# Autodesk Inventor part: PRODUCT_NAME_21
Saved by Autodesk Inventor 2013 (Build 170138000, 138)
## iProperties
Created: 2012-12
Part Number: PRODUCT_NAME_21
Material: Générique
Document SubType Name: Modeling
Designer: jost thierry
Density: 1 g/cm^3
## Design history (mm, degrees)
node "PRODUCT_NAME_211"
node "PRODUCT_NAME_21"
node "Base1"
